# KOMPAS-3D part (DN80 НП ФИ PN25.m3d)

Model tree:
1. Операция без истории:1

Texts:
  DN80 НП ФИ PN25
  133 1 134 1 135 1 136 0 50 1|SPDS|133 1 134 1 135 1 136 0 50 1
  125 1 126 1 127 1 128 0 50 1|SPDS|125 1 126 1 127 1 128 0 50 1
  129 1 130 1 131 1 132 0 50 1|SPDS|129 1 130 1 131 1 132 0 50 1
